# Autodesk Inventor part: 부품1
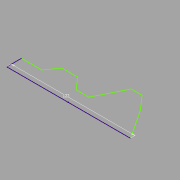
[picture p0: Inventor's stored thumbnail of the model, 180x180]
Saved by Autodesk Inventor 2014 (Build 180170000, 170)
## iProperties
Created: 2015-05
Part Number: 부품1
Material: Generic
Document SubType Name: Modeling
Designer: Administrator
Density: 1 g/cm^3
Appearance: Default
Author: Administrator
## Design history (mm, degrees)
sketch "스케치1"
  geometry: L1 (-61, 0)-(61, 0); L2 (-61, 0)-(-61, 14.596); L3 (-61, 14.596)-(-41.057, 14.596); L4 (-41.057, 14.596)-(-32.654, 26.186); L5 (-32.654, 26.186)-(-17.296, 26.186); L6 (-17.296, 26.186)-(-7.154, 14.596); L7 (-7.154, 14.596)-(5.305, 14.596); L8 (5.305, 14.596)-(19.214, 42.413); L9 (19.214, 42.413)-(29.935, 42.413); L10 (29.935, 42.413)-(42.105, 28.504); L11 (42.105, 28.504)-(61, 0); 2 further points
  constraints: 22 end point, 4 parallel, 2 perpendicular, 1 coincident, 1 horizontal, 1 midpoint
  dimensions: "d0" = 122 distance of L1.start L1.end
